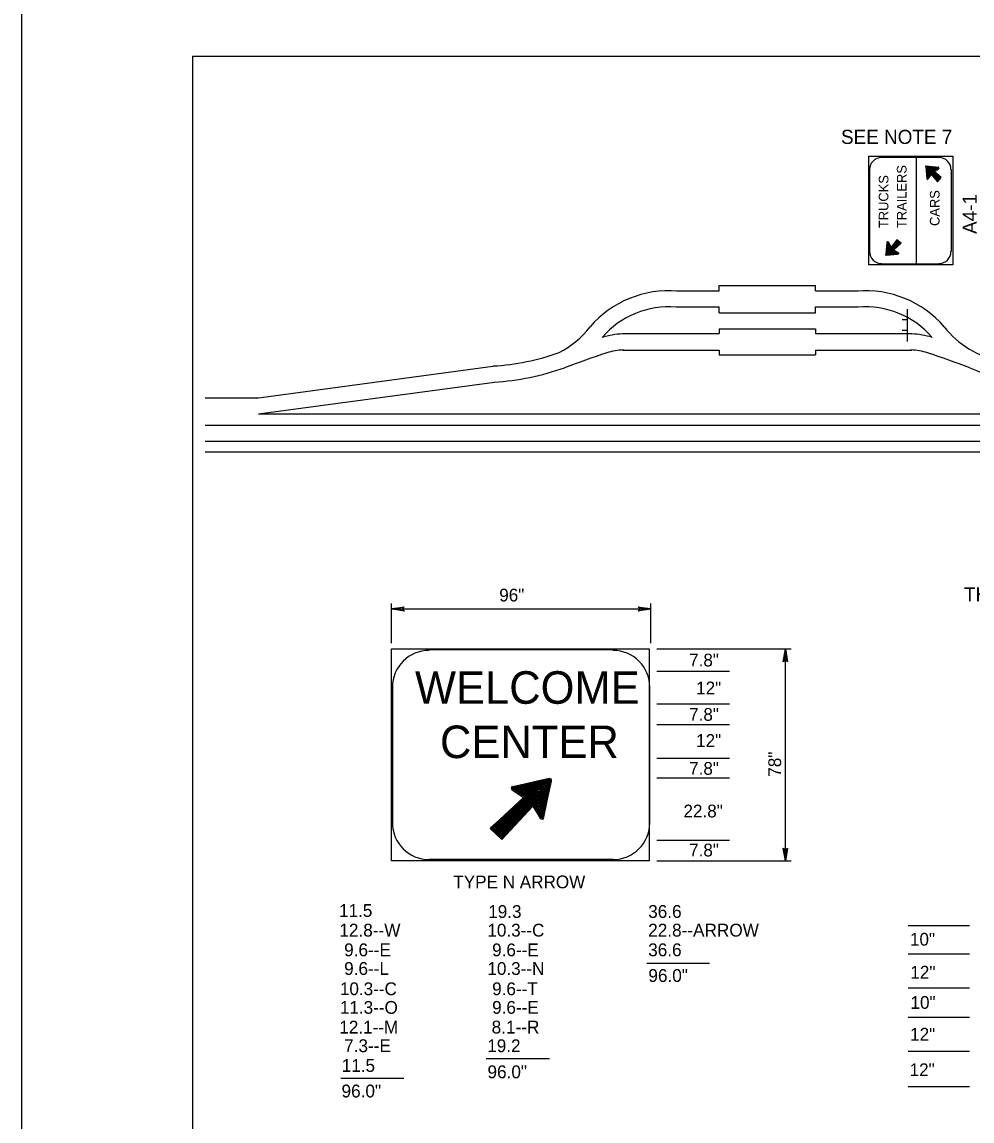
# Model space of a CAD drawing. Extents: x 638689 to 652291, y 298458 to 299646.
# Drawn here: x 651386.3 to 651609.3, y 298786.8 to 299044.7 of the extents above; entities that cross this region are included whole.
import ezdxf

# ---------------------------------------------------------------- set-up
doc = ezdxf.new("R2010")
doc.units = 0
for name, color, linetype in [('1', 7, 'Continuous'), ('2', 7, 'Continuous'), ('3', 7, 'Continuous'), ('PLT-BNDY', 7, 'Continuous')]:
    doc.layers.add(name, color=color, linetype=linetype)

# ---------------------------------------------------------------- blocks, each defined once
blk = doc.blocks.new('RARROW')
at = {"layer": '3'}
blk.add_lwpolyline([(-2.2695, 0.285), (-2.184875, 0.12075), (0, 0), (-2.2695, 0.285), (-2.38575, 0.384625), (0, 0), (-2.183125, -0.108), (-2.262875, -0.2705), (0, 0), (-2.38575, -0.379125), (-2.262875, -0.2705)], dxfattribs=at)

msp = doc.modelspace()

# ---------------------------------------------------------------- linework, layer by layer
at = {"layer": '1'}
for q in [(652212.31, 299036.75), (651426.31, 298472.75)]:
    msp.add_line((651426.31, 299036.75), q, dxfattribs=at)
at = {"layer": '2'}
for p, q in [((651588.06, 299013), (651601.56, 299013)), ((651596.31, 298988), (651596.31, 299013)), ((651598.44, 299010.75), (651598.69, 299008)), ((651601.44, 299010.62), (651598.56, 299010.87)), ((651598.56, 299010.75), (651598.56, 299010.75)), ((651600.06, 299009.37), (651600.06, 299009.37)), ((651600.44, 299009.62), (651601.44, 299010.25)), ((651600.44, 299009.62), (651600.44, 299009.62)), ((651602.06, 299008.25), (651600.44, 299009.62)), ((651601.44, 299010.37), (651601.44, 299010.37)), ((651601.69, 299010.37), (651601.69, 299010.37)), ((651601.69, 299010.37), (651601.69, 299010.37)), ((651598.81, 299008), (651598.81, 299008)), ((651598.81, 299007.62), (651598.81, 299007.62)), ((651598.81, 299007.62), (651598.81, 299007.62)), ((651599.69, 299009), (651599.06, 299008)), ((651599.69, 299009), (651599.69, 299009)), ((651599.69, 299009), (651601.19, 299007.25)), ((651601.19, 299007.25), (651602.06, 299008.25)), ((651601.19, 299007.25), (651601.19, 299007.25)), ((651602.06, 299008.25), (651602.06, 299008.25)), ((651589.31, 298993), (651589.06, 298990.25)), ((651589.56, 298993.25), (651589.56, 298993.25)), ((651589.56, 298993.25), (651589.56, 298993.25)), ((651589.56, 298993), (651589.56, 298993)), ((651590.31, 298991.87), (651589.69, 298993.12)), ((651591.69, 298993.62), (651590.31, 298991.87)), ((651590.31, 298991.87), (651590.31, 298991.87)), ((651590.56, 298991.62), (651590.56, 298991.62)), ((651590.94, 298991.25), (651592.69, 298992.87)), ((651591.69, 298993.62), (651591.69, 298993.62)), ((651592.69, 298992.87), (651591.69, 298993.62)), ((651592.69, 298992.87), (651592.69, 298992.87)), ((651589.06, 298990.12), (651589.06, 298990.12)), ((651589.06, 298990.12), (651589.06, 298990.12)), ((651589.19, 298990.25), (651589.19, 298990.25)), ((651589.19, 298990), (651591.94, 298990.25)), ((651590.94, 298991.25), (651590.94, 298991.25)), ((651590.94, 298991.25), (651591.94, 298990.62)), ((651591.94, 298990.5), (651591.94, 298990.5)), ((651592.19, 298990.5), (651592.19, 298990.5)), ((651592.19, 298990.5), (651592.19, 298990.5)), ((651587.69, 298987.75), (651585.81, 298987.75)), ((651588.06, 298988), (651601.56, 298988)), ((651596.81, 298987.75), (651595.44, 298987.75)), ((651539.94, 298981.62), (651549.94, 298981.62)), ((651549.94, 298982.87), (651572.56, 298982.87)), ((651549.94, 298981.62), (651549.94, 298982.87)), ((651572.56, 298981.62), (651572.56, 298982.87)), ((651572.56, 298981.62), (651582.56, 298981.62)), ((651539.94, 298977.87), (651549.94, 298977.87)), ((651549.94, 298976.5), (651549.94, 298977.87)), ((651549.94, 298976.5), (651572.56, 298976.5)), ((651572.56, 298976.5), (651572.56, 298977.87)), ((651572.56, 298977.87), (651582.56, 298977.87)), ((651594.19, 298969.75), (651594.19, 298977.37)), ((651594.19, 298974.87), (651592.94, 298974.87)), ((651527.31, 298971.62), (651549.94, 298971.62)), ((651549.94, 298972.75), (651572.56, 298972.75)), ((651549.94, 298972.75), (651549.94, 298971.62)), ((651572.56, 298972.75), (651572.56, 298971.62)), ((651572.56, 298971.62), (651595.19, 298971.62)), ((651594.19, 298972.37), (651592.94, 298972.37)), ((651527.31, 298967.75), (651549.94, 298967.75)), ((651549.94, 298967.75), (651549.94, 298966.62)), ((651549.94, 298966.62), (651572.56, 298966.62)), ((651572.56, 298967.75), (651572.56, 298966.62)), ((651572.56, 298967.75), (651595.19, 298967.75)), ((651441.31, 298956.5), (651496.81, 298964)), ((651441.81, 298952.75), (651497.19, 298960.25)), ((651497.19, 298960.25), (651497.19, 298960.25)), ((651497.19, 298960.25), (651497.19, 298960.25)), ((651441.81, 298956.5), (651429.31, 298956.5)), ((651441.81, 298952.75), (651680.69, 298952.75)), ((651441.81, 298952.75), (651441.81, 298952.75)), ((651441.81, 298952.75), (651441.81, 298952.75)), ((651429.31, 298950.12), (652211.31, 298950.12)), ((651429.31, 298946.37), (652211.31, 298946.37)), ((651429.31, 298943.87), (652211.31, 298943.87)), ((651473.06, 298899), (651473.06, 298908.25)), ((651473.06, 298907), (651533.94, 298907)), ((651533.94, 298899), (651533.94, 298908.25)), ((651535.31, 298897.62), (651566.9, 298897.62)), ((651565.52, 298847.87), (651565.52, 298897.62)), ((651535.31, 298892.37), (651552.39, 298892.37)), ((651473.31, 298888.75), (651473.31, 298856.75)), ((651533.69, 298856.75), (651533.69, 298888.75)), ((651535.31, 298884.75), (651552.39, 298884.75)), ((651535.31, 298879.87), (651552.39, 298879.87)), ((651535.31, 298872), (651552.39, 298872)), ((651500.56, 298865.12), (651500.56, 298865.12)), ((651510.06, 298867.25), (651501.56, 298865.25)), ((651508.81, 298858.12), (651510.56, 298866.5)), ((651510.69, 298867.37), (651510.69, 298867.37)), ((651535.31, 298867.37), (651552.39, 298867.37)), ((651504.06, 298862.75), (651496.19, 298855.5)), ((651501.44, 298864.5), (651504.06, 298862.75)), ((651504.06, 298862.75), (651504.06, 298862.75)), ((651498.94, 298852.87), (651506.19, 298860.75)), ((651506.19, 298860.75), (651506.19, 298860.75)), ((651506.19, 298860.75), (651507.94, 298857.87)), ((651496.19, 298855.5), (651498.94, 298852.87)), ((651508.56, 298856.87), (651508.56, 298856.87)), ((651535.31, 298852.75), (651552.39, 298852.75)), ((651535.31, 298847.87), (651566.9, 298847.87)), ((651608.69, 298832.62), (651594.33, 298832.62)), ((651608.69, 298825.99), (651594.33, 298825.99)), ((651608.69, 298817.99), (651594.33, 298817.99)), ((651608.69, 298811.12), (651594.33, 298811.12)), ((651608.69, 298803.12), (651594.33, 298803.12)), ((651608.69, 298794.87), (651594.33, 298794.87))]:
    msp.add_line(p, q, dxfattribs=at)
for points in [[(651585.06, 298987.75), (651585.06, 299013.25), (651586.81, 299013.25), (651589.06, 299013.25), (651590.69, 299013.25), (651593.06, 299013.25), (651594.69, 299013.25), (651596.56, 299013.25), (651600.31, 299013.25), (651604.81, 299013.25), (651604.81, 298987.75), (651599.44, 298987.75), (651597.31, 298987.75), (651594.69, 298987.75), (651591.81, 298987.75), (651588.06, 298987.75), (651585.06, 298987.75)], [(651585.31, 298990.87), (651585.31, 299010.12)], [(651598.44, 299010.75), (651598.81, 299008.12), (651598.81, 299008), (651598.94, 299007.87), (651598.94, 299008), (651599.69, 299009.12), (651599.69, 299009.12), (651601.19, 299007.37), (651601.94, 299008.25), (651600.31, 299009.62), (651600.31, 299009.62), (651601.44, 299010.37), (651601.56, 299010.37), (651601.44, 299010.5), (651601.44, 299010.5), (651598.56, 299010.87), (651598.56, 299010.87), (651598.44, 299010.75), (651598.56, 299010.75), (651598.81, 299008), (651599.56, 299009.12), (651601.19, 299007.5), (651601.94, 299008.25), (651600.19, 299009.62), (651601.44, 299010.5), (651598.56, 299010.75), (651598.81, 299008.12), (651599.56, 299009.25), (651601.19, 299007.5), (651601.81, 299008.25), (651600.19, 299009.62), (651601.44, 299010.37), (651598.56, 299010.75), (651598.94, 299008.25), (651599.56, 299009.25), (651601.19, 299007.62), (651601.69, 299008.25), (651600.19, 299009.62), (651601.31, 299010.37), (651598.69, 299010.62), (651598.94, 299008.37), (651599.56, 299009.37), (651601.19, 299007.62), (651601.69, 299008.25), (651600.06, 299009.62), (651601.19, 299010.37), (651598.69, 299010.62), (651598.94, 299008.5), (651599.56, 299009.37), (651601.19, 299007.87), (651601.56, 299008.25), (651600.06, 299009.62), (651600.94, 299010.37), (651598.81, 299010.62), (651599.06, 299008.62), (651599.56, 299009.5), (651601.19, 299008), (651601.56, 299008.25), (651599.94, 299009.62), (651600.94, 299010.25), (651598.81, 299010.5), (651599.06, 299008.75), (651599.56, 299009.5), (651601.19, 299008), (651601.44, 299008.25), (651599.94, 299009.75), (651600.69, 299010.25), (651598.81, 299010.5), (651599.06, 299008.87), (651599.56, 299009.62), (651601.19, 299008.12), (651601.44, 299008.25), (651599.94, 299009.75), (651600.56, 299010.25), (651598.94, 299010.37), (651599.06, 299009), (651599.56, 299009.62), (651601.19, 299008.12), (651601.31, 299008.25), (651599.69, 299009.75), (651600.44, 299010.12), (651599.06, 299010.37), (651599.19, 299009.25), (651599.56, 299009.75), (651601.19, 299008.25), (651601.31, 299008.25), (651599.69, 299009.75), (651600.31, 299010.12), (651599.06, 299010.25), (651599.19, 299009.37), (651599.56, 299009.75), (651601.19, 299008.25), (651599.56, 299009.87), (651600.19, 299010.12), (651599.06, 299010.25), (651599.19, 299009.37), (651599.56, 299009.87), (651600.44, 299009.12), (651599.56, 299009.87), (651600.19, 299010.12), (651599.19, 299010.12)], [(651599.19, 299010.12), (651599.19, 299009.62), (651600.06, 299010.12), (651599.19, 299010.12), (651599.31, 299009.62), (651599.94, 299010), (651599.31, 299010.12), (651599.31, 299009.75), (651599.69, 299010), (651599.31, 299010), (651599.31, 299009.87), (651599.56, 299010), (651599.31, 299010), (651599.31, 299009.87), (651599.44, 299010)], [(651604.44, 299010.12), (651604.44, 298990.87)], [(651589.19, 298990.12), (651591.81, 298990.37), (651591.94, 298990.37), (651592.06, 298990.5), (651591.94, 298990.62), (651590.81, 298991.25), (651590.81, 298991.37), (651592.56, 298992.87), (651591.69, 298993.62), (651590.31, 298991.87), (651590.31, 298991.87), (651589.56, 298993.12), (651589.56, 298993.12), (651589.44, 298993.12), (651589.44, 298993), (651589.06, 298990.25), (651589.06, 298990.12), (651589.19, 298990.12), (651589.19, 298990.12), (651591.94, 298990.5), (651590.81, 298991.25), (651592.44, 298992.87), (651591.69, 298993.5), (651590.31, 298991.75), (651589.44, 298993.12), (651589.19, 298990.12), (651591.81, 298990.5), (651590.69, 298991.25), (651592.44, 298992.87), (651591.69, 298993.37), (651590.31, 298991.75), (651589.56, 298993), (651589.19, 298990.25), (651591.69, 298990.5), (651590.69, 298991.25), (651592.19, 298992.87), (651591.69, 298993.37), (651590.31, 298991.62), (651589.56, 298992.87), (651589.31, 298990.25), (651591.56, 298990.62), (651590.56, 298991.25), (651592.19, 298992.87), (651591.69, 298993.37), (651590.31, 298991.62), (651589.56, 298992.62), (651589.31, 298990.37), (651591.44, 298990.62), (651590.56, 298991.25), (651592.06, 298992.87), (651591.69, 298993.25), (651590.31, 298991.5), (651589.56, 298992.5), (651589.31, 298990.37), (651591.31, 298990.62), (651590.44, 298991.25), (651591.94, 298992.87), (651591.69, 298993.12), (651590.31, 298991.5), (651589.69, 298992.37), (651589.44, 298990.5), (651591.19, 298990.75), (651590.44, 298991.25), (651591.94, 298992.87), (651591.69, 298993.12), (651590.19, 298991.5), (651589.69, 298992.25), (651589.44, 298990.5), (651591.06, 298990.75), (651590.31, 298991.25), (651591.81, 298992.87), (651591.69, 298993), (651590.19, 298991.37), (651589.69, 298992.12), (651589.56, 298990.5), (651590.81, 298990.75), (651590.31, 298991.25), (651591.81, 298992.87), (651591.69, 298993), (651590.19, 298991.37), (651589.81, 298992), (651589.56, 298990.62), (651590.69, 298990.75), (651590.19, 298991.25), (651591.69, 298992.87), (651591.69, 298992.87), (651590.19, 298991.25), (651589.81, 298991.87), (651589.69, 298990.75), (651590.56, 298990.75), (651590.19, 298991.25), (651591.69, 298992.87), (651590.06, 298991.25), (651589.81, 298991.75), (651589.69, 298990.75), (651590.56, 298990.87), (651590.06, 298991.12), (651590.81, 298991.87), (651590.06, 298991.25), (651589.81, 298991.62), (651589.81, 298990.75)], [(651589.81, 298990.75), (651590.31, 298990.87), (651589.81, 298991.5), (651589.81, 298990.87), (651590.31, 298990.87), (651589.94, 298991.5), (651589.81, 298990.87), (651590.19, 298991), (651589.94, 298991.25), (651589.94, 298991), (651590.06, 298991), (651589.94, 298991.25), (651589.94, 298991), (651590.06, 298991), (651589.94, 298991.12)], [(651525.06, 298897.37), (651481.94, 298897.37)], [(651496.31, 298855.62), (651504.44, 298862.87), (651501.44, 298864.75), (651501.31, 298864.87), (651501.56, 298865.25), (651510.19, 298867.12), (651510.56, 298867), (651510.56, 298866.62), (651508.69, 298858.12), (651508.44, 298857.87), (651508.06, 298858), (651506.19, 298860.87), (651498.94, 298853), (651496.56, 298855.5), (651504.56, 298862.87), (651501.44, 298864.87), (651501.44, 298864.87), (651501.56, 298865.25), (651510.19, 298867), (651510.31, 298866.87), (651510.44, 298866.62), (651508.56, 298858.25), (651508.31, 298858), (651508.06, 298858), (651506.19, 298861), (651498.81, 298853.12), (651496.69, 298855.5), (651504.69, 298862.75), (651501.56, 298864.87), (651501.56, 298865), (651501.56, 298865.12), (651510.31, 298866.75), (651508.31, 298858.12), (651506.19, 298861.25), (651498.81, 298853.25), (651496.94, 298855.5), (651504.69, 298862.75), (651501.56, 298865), (651510.19, 298866.62)], [(651501.69, 298864.87), (651510.19, 298866.5), (651508.31, 298858.25), (651506.19, 298861.62), (651498.69, 298853.37), (651497.06, 298855.5), (651504.81, 298862.87), (651502.19, 298864.87), (651509.94, 298866.37), (651508.19, 298858.5), (651506.31, 298861.87), (651498.69, 298853.75), (651497.44, 298855.5), (651505.06, 298862.87), (651502.69, 298864.75), (651509.69, 298866.12), (651508.06, 298859), (651506.31, 298862), (651498.69, 298853.87), (651497.69, 298855.62), (651505.19, 298862.87), (651503.19, 298864.62), (651509.56, 298866), (651507.94, 298859.5), (651506.31, 298862.12), (651498.81, 298854.25), (651497.94, 298855.62), (651505.44, 298862.87), (651503.56, 298864.5), (651509.31, 298865.62), (651507.94, 298859.87), (651506.31, 298862.37), (651498.81, 298854.62), (651498.31, 298855.62), (651505.56, 298862.87), (651503.94, 298864.37), (651509.06, 298865.37), (651507.81, 298860.37), (651506.31, 298862.5), (651498.94, 298855.12), (651498.81, 298855), (651498.44, 298855.5), (651505.81, 298862.87), (651504.44, 298864.25), (651508.81, 298865.25), (651507.56, 298860.75), (651506.31, 298862.62), (651498.81, 298855.12), (651498.56, 298855.5), (651506.06, 298862.87), (651504.81, 298864.25), (651508.44, 298865), (651507.56, 298861.25), (651506.31, 298862.87), (651498.69, 298855.25), (651498.69, 298855.5), (651506.19, 298862.87), (651505.06, 298864.12), (651508.31, 298864.87), (651507.56, 298861.5), (651505.44, 298864), (651508.06, 298864.62), (651507.44, 298861.87), (651505.81, 298864), (651507.81, 298864.25), (651507.31, 298862), (651506.06, 298863.75), (651507.56, 298864.12), (651507.31, 298862.5), (651506.44, 298863.62), (651507.44, 298864), (651507.19, 298862.87), (651506.81, 298863.5), (651507.19, 298863.62), (651507.06, 298863.25)], [(651481.94, 298848.25), (651525.06, 298848.25)]]:
    msp.add_lwpolyline(points, dxfattribs=at)
msp.add_lwpolyline([(651473.06, 298847.87), (651473.06, 298897.62), (651533.56, 298897.62), (651533.56, 298847.87)], close=True, dxfattribs=at)
for centre, radius, start, end in [((651588.1, 299010.1), 2.83, 90, 180), ((651601.55, 299010.1), 2.83, 0, 90), ((651598.6, 299010.75), 0.177, 84.0498, 185.9502), ((651601.38, 299010.46), 0.177, 301.5539, 84.0498), ((651598.89, 299007.98), 0.177, 185.9502, 328.4461), ((651589.47, 298992.95), 0.177, 31.5539, 174.0498), ((651588.1, 298990.87), 2.83, 180, 270), ((651589.18, 298990.17), 0.177, 174.0498, 275.9502), ((651591.95, 298990.46), 0.177, 275.9502, 58.4461), ((651601.55, 298990.87), 2.83, 270, 0), ((651538.2, 298957.14), 24.54, 85.4134, 139.1043), ((651584.26, 298957.14), 24.54, 40.8957, 94.5866), ((651538.2, 298957.14), 20.77, 85.4134, 139.1043), ((651584.26, 298957.14), 20.77, 40.8957, 94.5866), ((651502.66, 298986.34), 21.48, 296.8793, 322.3109), ((651528.36, 298950.96), 20.62, 92.9526, 106.4866), ((651594.11, 298950.96), 20.62, 73.5134, 87.0474), ((651619.81, 298986.34), 21.48, 217.6891, 259.2048), ((651493.68, 299019.5), 55.58, 273.3346, 289.6636), ((654118.4, 291624.64), 7787.51, 109.463364, 109.540836), ((651528.36, 298950.96), 16.85, 92.9526, 106.4866), ((651594.11, 298950.96), 16.85, 73.5134, 87.0474), ((649004.06, 291624.64), 7787.51, 70.459164, 70.536636), ((651493.68, 299019.5), 59.35, 273.3346, 289.6636), ((651619.81, 298986.34), 25.25, 244.1957, 259.2048), ((651481.91, 298888.64), 8.64, 90, 180), ((651525.03, 298888.64), 8.64, 0, 90), ((651501.62, 298864.9), 0.477, 101.9042, 237.308), ((651501.62, 298864.9), 0.477, 101.9043, 237.308), ((651510.17, 298866.71), 0.477, 348.0958, 101.9043), ((651510.17, 298866.71), 0.477, 348.0958, 101.9043), ((651508.37, 298858.16), 0.477, 212.692, 348.0958), ((651508.37, 298858.16), 0.477, 212.692, 348.0958), ((651481.91, 298856.82), 8.64, 180, 270), ((651525.03, 298856.82), 8.64, 270, 0)]:
    msp.add_arc(centre, radius, start, end, dxfattribs=at)
at = {"layer": '3'}
for p, q in [((651532.98, 298823.89), (651547.7, 298823.89)), ((651495.27, 298801.52), (651510.15, 298801.52)), ((651461.13, 298796.87), (651475.91, 298796.87))]:
    msp.add_line(p, q, dxfattribs=at)
at = {"layer": 'PLT-BNDY'}
msp.add_lwpolyline([(651386.31, 299051.75), (652227.31, 299051.75), (652227.31, 298457.75), (651386.31, 298457.75)], close=True, dxfattribs=at)

# ---------------------------------------------------------------- block references
at = {"layer": '2', "xscale": 1.2574347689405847, "yscale": 1.3092961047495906}
for p, rotation in [((651473.06, 298907), 180), ((651565.52, 298897.62), 89.99999999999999), ((651565.52, 298847.87), -90.00000000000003)]:
    msp.add_blockref('RARROW', p, dxfattribs=dict(at, rotation=rotation))
msp.add_blockref('RARROW', (651533.94, 298907), dxfattribs=at)

# ---------------------------------------------------------------- texts
at = {"layer": '2'}
for s, height, p in [('SEE NOTE 7', 3.317, (651578.56, 299016.12)), ('96"', 3, (651498.34, 298908.76)), ('THEORETICAL GORE', 3.3173, (651607.44, 298908.75)), ('7.8"', 3, (651542.91, 298893.5)), ('WELCOME', 7.634, (651478.56, 298884.75)), ('12"', 3, (651544.56, 298886.96)), ('7.8"', 3, (651542.91, 298880.75)), ('CENTER', 7.634, (651484.44, 298872)), ('12"', 3, (651544.56, 298874.63)), ('7.8"', 3, (651542.91, 298868.08)), ('22.8"', 3, (651541.58, 298858.08)), ('7.8"', 3, (651542.91, 298848.92)), ('TYPE N ARROW', 3, (651487.56, 298841.45)), ('11.5', 3, (651460.74, 298834.73)), ('19.3', 3, (651495.76, 298834.5)), ('36.6       ', 3.0158, (651533.3, 298834.5)), ('12.8--W', 3.016, (651460.81, 298830.12)), ('10.3--C', 3, (651495.56, 298830.12)), ('22.8--ARROW', 3.0158, (651533.3, 298830.12)), ('10"', 3, (651594.75, 298827.99)), (' 9.6--E', 3.016, (651460.81, 298825.5)), (' 9.6--E', 3, (651495.56, 298825.5)), ('36.6       ', 3.0158, (651533.3, 298825.5)), (' 9.6--L', 3.016, (651460.81, 298821.12)), ('10.3--N', 3, (651495.56, 298821.12)), ('96.0"        ', 3.0158, (651533.35, 298819.47)), ('12"', 3, (651594.84, 298820.25)), ('10.3--C', 3, (651460.94, 298816.37)), (' 9.6--T', 3, (651495.56, 298816.37)), ('10"', 3, (651594.88, 298813.16)), ('11.3--O', 3, (651460.94, 298812)), (' 9.6--E', 3, (651495.56, 298812)), ('12.1--M', 3, (651460.81, 298807.37)), (' 8.1--R', 3.016, (651495.44, 298807.37)), ('12"', 3, (651594.79, 298805.7)), (' 7.3--E', 3.016, (651460.81, 298803)), ('19.2', 3, (651495.53, 298803)), ('11.5  ', 3, (651461.37, 298798.37)), ('96.0"     ', 3.016, (651495.58, 298796.87)), ('12"', 3, (651594.67, 298797.37)), ('96.0"', 3.016, (651461.32, 298792.37))]:
    msp.add_text(s, height=height, dxfattribs=at).set_placement(p)
for s, height, p in [('TRAILERS', 2.261, (651593.94, 298996.37)), ('TRUCKS', 2.261, (651589.69, 298996.37)), ('CARS', 2.261, (651601.69, 298996.87)), ('A4-1', 3.318, (651610.44, 298995)), ('78"', 3, (651564.5, 298867.63))]:
    msp.add_text(s, height=height, rotation=90, dxfattribs=at).set_placement(p)

doc.saveas('drawing.dxf')
